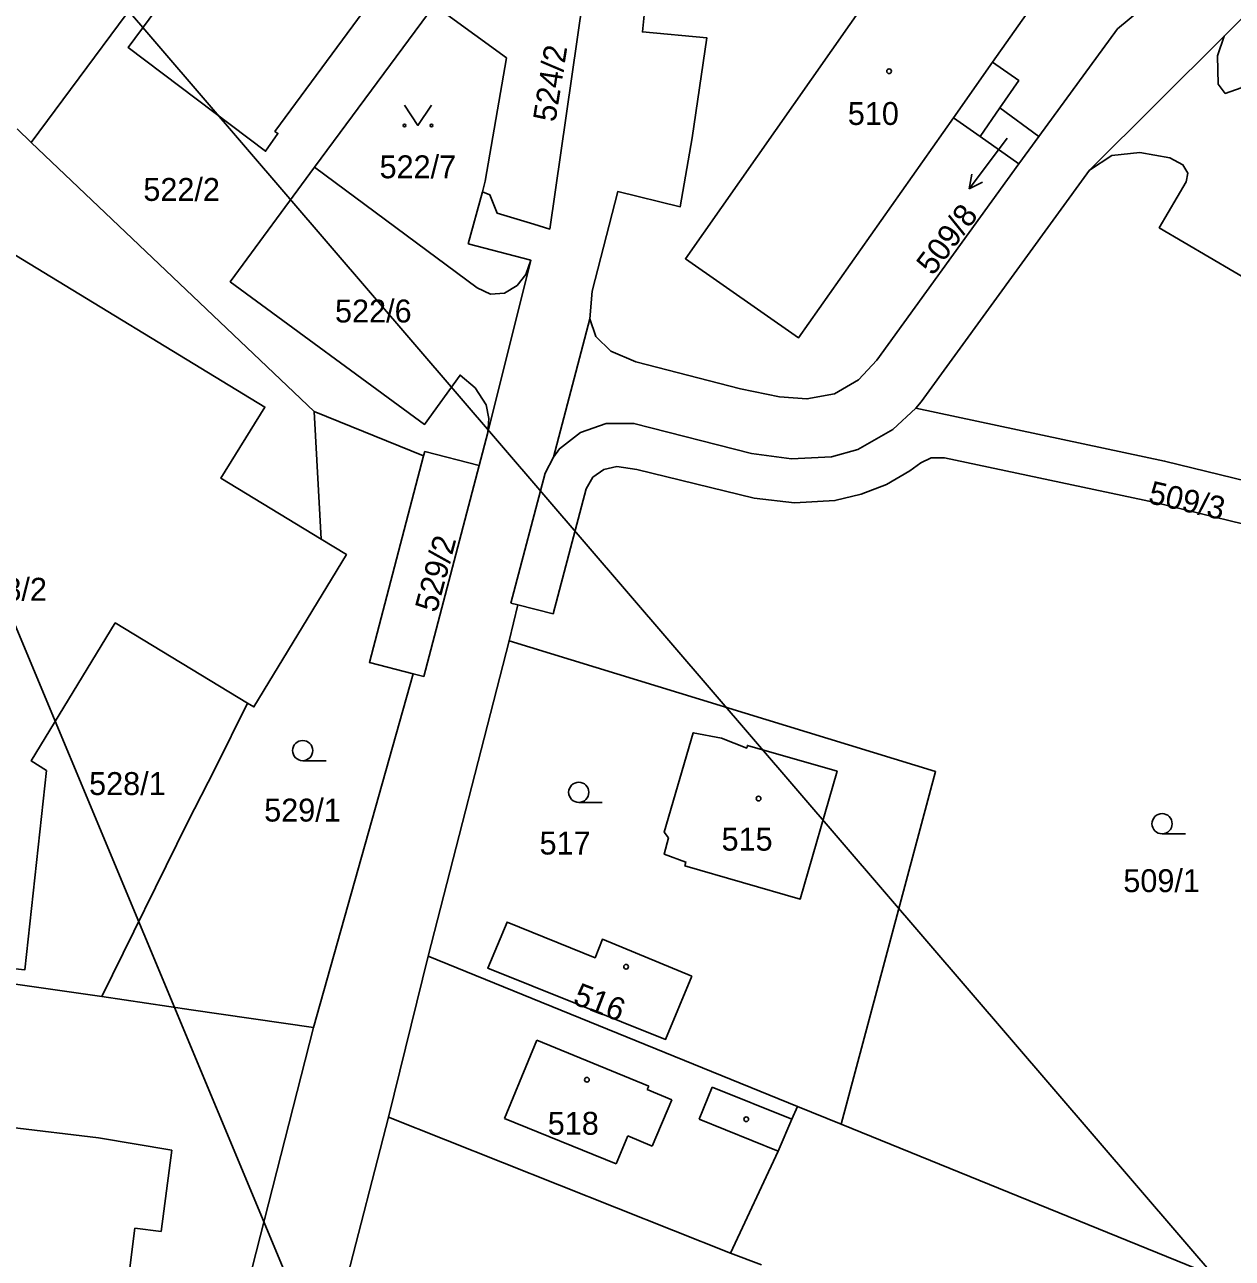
# Model space of a CAD drawing. Extents: x -558358 to -557517, y -1073786 to -1073189.
# Drawn here: x -558108 to -558018.3, y -1073559.5 to -1073467.9 of the extents above; entities that cross this region are included whole.
import ezdxf

# ---------------------------------------------------------------- set-up
doc = ezdxf.new("R2010")
doc.units = 0
for name, color, linetype in [('Hranice parcel', 7, 'Continuous'), ('Parcelní čísla', 7, 'Continuous'), ('Pop  PČ popisy', 7, 'Continuous'), ('Vnitřní kresba', 7, 'Continuous'), ('Vrstva 28', 7, 'Continuous'), ('Značky budov', 7, 'Continuous'), ('Značky kultur', 7, 'Continuous')]:
    doc.layers.add(name, color=color, linetype=linetype)

msp = doc.modelspace()

# ---------------------------------------------------------------- linework, layer by layer
at = {"layer": 'Hranice parcel'}
for p, q in [((-558086.45, -1073478.46), (-558077.57, -1073466.44)), ((-558076.9, -1073466.92), (-558072.2, -1073470.34)), ((-558018.89, -1073468.72), (-558028.88, -1073478.68)), ((-558072.2, -1073470.34), (-558073.77, -1073479.5)), ((-558037.01, -1073476.18), (-558035.54, -1073474.05)), ((-558032.65, -1073476.17), (-558035.54, -1073474.05)), ((-558108.55, -1073475.6), (-558107.49, -1073476.62)), ((-558107.49, -1073476.62), (-558086.48, -1073496.61)), ((-558037.01, -1073476.18), (-558034.12, -1073478.2)), ((-558032.65, -1073476.17), (-558034.12, -1073478.2)), ((-558073.77, -1073479.5), (-558073.98, -1073480.28)), ((-558073.98, -1073480.28), (-558075.03, -1073484.15)), ((-558075.03, -1073484.15), (-558070.38, -1073485.35)), ((-558070.38, -1073485.35), (-558073.57, -1073498.15)), ((-558068.7, -1073499.98), (-558066, -1073489.71)), ((-558085.97, -1073506.08), (-558086.48, -1073496.61)), ((-558086.48, -1073496.61), (-558078.35, -1073499.89)), ((-558074.22, -1073500.6), (-558073.57, -1073498.15)), ((-558078.35, -1073499.89), (-558078.27, -1073499.57)), ((-558078.27, -1073499.57), (-558074.22, -1073500.6)), ((-558074.22, -1073500.6), (-558078.34, -1073516.28)), ((-558071.35, -1073510.96), (-558071.87, -1073510.83)), ((-558071.35, -1073510.96), (-558072, -1073513.63)), ((-558068.72, -1073511.63), (-558071.35, -1073510.96)), ((-558072, -1073513.63), (-558078.01, -1073537.04)), ((-558079.12, -1073516.08), (-558086.54, -1073542.34)), ((-558078.34, -1073516.28), (-558079.12, -1073516.08)), ((-558102.24, -1073540.03), (-558132.14, -1073535.81)), ((-558078.01, -1073537.04), (-558080.96, -1073549.01)), ((-558078.01, -1073537.04), (-558050.57, -1073548.21)), ((-558050.57, -1073548.21), (-558047.33, -1073549.53)), ((-558080.96, -1073549.01), (-558086.83, -1073571.83)), ((-558080.96, -1073549.01), (-558055.56, -1073559.09)), ((-558055.56, -1073559.09), (-558053.26, -1073559.97))]:
    msp.add_line(p, q, dxfattribs=at)
for points in [[(-558066, -1073489.71), (-558065.83, -1073487.66), (-558063.93, -1073480.27), (-558059.28, -1073481.39), (-558058.41, -1073476.28), (-558057.32, -1073468.85), (-558062.09, -1073468.41), (-558061.69, -1073464.41), (-558056.9, -1073464.79), (-558056.8, -1073459.32), (-558057.06, -1073454.51), (-558057.72, -1073449.34), (-558062.47, -1073450), (-558063.26, -1073446.76)], [(-558069.01, -1073448.19), (-558089.39, -1073475.8), (-558089.17, -1073475.95), (-558090.09, -1073477.27), (-558100.29, -1073469.58), (-558095.61, -1073463.24)], [(-558018.89, -1073468.72), (-558017.43, -1073467.28), (-558004.36, -1073462.2), (-558000.71, -1073460.54), (-557997.38, -1073458.33), (-557994.81, -1073455.9), (-557993.5, -1073454.4)], [(-558035.54, -1073474.05), (-558034.14, -1073472.03), (-558036.08, -1073470.66), (-558030.24, -1073462.37), (-558038.66, -1073456.4), (-558058.9, -1073485.25), (-558050.49, -1073491.12), (-558038.98, -1073474.78), (-558037.01, -1073476.18)], [(-558066.82, -1073460.61), (-558066.53, -1073466.05), (-558068.98, -1073483.05), (-558070.17, -1073482.68), (-558072.89, -1073481.86), (-558073.42, -1073480.5), (-558073.98, -1073480.28)], [(-558095.61, -1073463.24), (-558096.89, -1073462.29), (-558107.49, -1073476.62)], [(-558022.54, -1073464.96), (-558025.08, -1073466.74), (-558026.8, -1073468.19), (-558032.65, -1073476.17)], [(-557958.67, -1073504.77), (-557959.52, -1073505.42), (-557960.94, -1073505.97), (-557962.48, -1073505.9), (-557963.93, -1073505.3), (-557964.34, -1073504.64), (-557964.29, -1073503.98), (-557962.25, -1073500.52), (-558015.64, -1073469.14), (-558017.62, -1073472.56), (-558018.8, -1073472.98), (-558019.32, -1073472.29), (-558019.38, -1073470.18), (-558018.89, -1073468.72)], [(-558028.88, -1073478.68), (-558027.22, -1073477.58), (-558025.14, -1073477.37), (-558022.91, -1073477.77), (-558021.94, -1073478.27), (-558021.58, -1073478.9), (-558021.69, -1073479.54), (-558023.7, -1073482.95), (-557975.42, -1073511.29), (-557973.41, -1073507.84), (-557972.71, -1073507.36), (-557971.95, -1073507.53), (-557966.49, -1073510.72), (-557965.39, -1073511.77), (-557964.96, -1073512.7), (-557964.79, -1073513.87)], [(-558073.57, -1073498.15), (-558073.51, -1073497.13), (-558073.7, -1073496.11), (-558074.52, -1073494.85), (-558075.64, -1073493.89), (-558078.28, -1073497.56), (-558092.71, -1073486.96), (-558086.45, -1073478.46)], [(-558070.38, -1073485.35), (-558070.76, -1073486.43), (-558071.41, -1073487.24), (-558072.33, -1073487.8), (-558073.38, -1073487.88), (-558074.36, -1073487.41), (-558086.45, -1073478.46)], [(-558034.12, -1073478.2), (-558044.67, -1073492.79), (-558046.03, -1073494.25), (-558047.82, -1073495.28), (-558049.88, -1073495.66), (-558051.92, -1073495.51), (-558054.81, -1073494.91), (-558062.59, -1073492.91), (-558064.44, -1073492.11), (-558065.56, -1073491.04), (-558066, -1073489.71)], [(-558028.88, -1073478.68), (-558041.38, -1073495.88), (-558041.79, -1073496.35)], [(-558091.42, -1073518.26), (-558101.25, -1073512.3), (-558107.5, -1073522.55), (-558106.36, -1073523.27), (-558107.97, -1073538.05), (-558111.12, -1073537.73), (-558112.87, -1073537.48), (-558114.81, -1073536.91), (-558116.94, -1073535.87), (-558118.99, -1073534.32), (-558120.94, -1073531.84), (-558122.18, -1073529.05), (-558122.71, -1073526.18), (-558122.56, -1073523.2), (-558121.01, -1073518.98), (-558124.91, -1073516.6), (-558126.01, -1073515.72), (-558126.67, -1073514.49), (-558126.79, -1073513.04), (-558126.28, -1073511.65), (-558109.74, -1073484.35), (-558090.14, -1073496.27), (-558093.41, -1073501.56), (-558085.97, -1073506.08)], [(-558068.7, -1073499.98), (-558068.26, -1073499.37), (-558066.7, -1073498.15), (-558064.79, -1073497.48), (-558062.72, -1073497.49), (-558053.98, -1073499.73), (-558051.03, -1073500.12), (-558048.06, -1073499.96), (-558046.1, -1073499.41), (-558043.49, -1073497.93), (-558041.79, -1073496.35)], [(-558041.79, -1073496.35), (-558023.3, -1073500.28), (-558002.91, -1073505.27), (-557995.6, -1073507.26), (-557965.43, -1073516.64)], [(-558078.35, -1073499.89), (-558082.38, -1073515.23), (-558079.12, -1073516.08)], [(-558071.87, -1073510.83), (-558069.32, -1073501.19), (-558068.7, -1073499.98)], [(-557987.27, -1073529.77), (-557989.29, -1073528.94), (-557986.56, -1073522.48), (-557986.36, -1073521.52), (-557986.44, -1073520.51), (-557989.6, -1073512.4), (-557996.64, -1073510.25), (-558004.14, -1073508.22), (-558024.01, -1073503.35), (-558039.66, -1073500.03), (-558040.64, -1073500.03), (-558041.42, -1073500.4), (-558042.23, -1073501), (-558043.97, -1073502.01), (-558045.84, -1073502.74), (-558047.8, -1073503.22), (-558050.8, -1073503.37), (-558053.79, -1073503.03), (-558062.52, -1073500.9), (-558063.99, -1073500.68), (-558064.96, -1073500.91), (-558065.77, -1073501.48), (-558066.28, -1073502.33), (-558068.72, -1073511.63)], [(-558091.42, -1073518.26), (-558090.96, -1073518.54), (-558084.08, -1073507.23), (-558085.97, -1073506.08)], [(-558047.33, -1073549.53), (-558040.31, -1073523.33), (-558072, -1073513.63)], [(-558102.24, -1073540.03), (-558095.9, -1073527.13), (-558093.83, -1073523.1), (-558091.42, -1073518.26)], [(-558060.16, -1073528.26), (-558060.48, -1073529.48), (-558058.86, -1073530.06), (-558058.94, -1073530.35), (-558050.37, -1073532.81), (-558047.63, -1073523.32), (-558054.29, -1073521.4), (-558054.34, -1073521.59), (-558056.23, -1073520.85), (-558058.32, -1073520.45), (-558060.47, -1073527.85), (-558060.16, -1073528.26)], [(-558058.43, -1073538.53), (-558065.06, -1073535.79), (-558065.61, -1073537.16), (-558072.15, -1073534.51), (-558073.59, -1073537.94), (-558060.37, -1073543.23), (-558058.43, -1073538.53)], [(-558086.54, -1073542.34), (-558095.62, -1073541.02), (-558102.24, -1073540.03)], [(-558099.6, -1073591.18), (-558091.09, -1073560.2), (-558086.54, -1073542.34)], [(-558055.56, -1073559.09), (-558052.02, -1073551.52), (-558051, -1073549.15), (-558050.57, -1073548.21)], [(-557977.41, -1073591.02), (-557981.5, -1073577.12), (-557984.25, -1073575.17), (-558047.33, -1073549.53)]]:
    msp.add_lwpolyline(points, dxfattribs=at)
at = {"layer": 'Pop  PČ popisy'}
for p, q in [((-558035, -1073476.29), (-558036.02, -1073477.67)), ((-558036.02, -1073477.67), (-558037.826, -1073480.067)), ((-558037.826, -1073480.067), (-558037.623, -1073478.966)), ((-558037.826, -1073480.067), (-558036.823, -1073479.568))]:
    msp.add_line(p, q, dxfattribs=at)
at = {"layer": 'Vnitřní kresba'}
for p, q in [((-558038.98, -1073474.78), (-558036.08, -1073470.66)), ((-558072.33, -1073549.11), (-558069.95, -1073543.28)), ((-558069.95, -1073543.28), (-558061.62, -1073546.69)), ((-558061.73, -1073546.96), (-558061.62, -1073546.69)), ((-558061.73, -1073546.96), (-558059.91, -1073547.71)), ((-558057.87, -1073549.14), (-558056.91, -1073546.78)), ((-558056.91, -1073546.78), (-558051, -1073549.15)), ((-558061.37, -1073551.16), (-558059.91, -1073547.71)), ((-558072.33, -1073549.11), (-558064.04, -1073552.48)), ((-558057.87, -1073549.14), (-558052.02, -1073551.52)), ((-558109.12, -1073549.75), (-558102.5, -1073550.54)), ((-558102.5, -1073550.54), (-558097.04, -1073551.46)), ((-558064.04, -1073552.48), (-558063.17, -1073550.4)), ((-558063.17, -1073550.4), (-558061.37, -1073551.16)), ((-558097.85, -1073557.5), (-558097.04, -1073551.46)), ((-558100.77, -1073564.79), (-558099.8, -1073557.24)), ((-558099.8, -1073557.24), (-558097.85, -1073557.5))]:
    msp.add_line(p, q, dxfattribs=at)
at = {"layer": 'Vrstva 28'}
for p, q in [((-558150.499, -1073408.333), (-557941.756, -1073651.484)), ((-558150.161, -1073413.052), (-558044.903, -1073665.427))]:
    msp.add_line(p, q, dxfattribs=at)
at = {"layer": 'Značky budov'}
for centre in [(-558043.767, -1073471.329), (-558053.467, -1073525.339), (-558063.307, -1073537.829), (-558066.217, -1073546.229), (-558054.377, -1073549.159)]:
    msp.add_circle(centre, 0.175, dxfattribs=at)
at = {"layer": 'Značky kultur'}
for p, q in [((-558087.333, -1073522.53), (-558085.583, -1073522.53)), ((-558066.823, -1073525.63), (-558065.073, -1073525.63)), ((-558023.493, -1073527.96), (-558021.743, -1073527.96))]:
    msp.add_line(p, q, dxfattribs=at)
msp.add_lwpolyline([(-558079.77, -1073473.859), (-558078.77, -1073475.36), (-558077.77, -1073473.859)], dxfattribs=at)
for centre, radius in [((-558079.77, -1073475.359), 0.1), ((-558077.77, -1073475.359), 0.1), ((-558087.333, -1073521.78), 0.75), ((-558066.823, -1073524.88), 0.75), ((-558023.493, -1073527.21), 0.75)]:
    msp.add_circle(centre, radius, dxfattribs=at)

# ---------------------------------------------------------------- texts
at = {"layer": 'Parcelní čísla'}
for s, rotation, p in [('524/2', 81, (-558068.556, -1073475.16)), ('509/8', 53, (-558040.516, -1073486.575)), ('509/3', 347, (-558024.595, -1073503.386)), ('529/2', 75, (-558077.378, -1073511.589)), ('516', 339, (-558067.335, -1073540.57))]:
    msp.add_text(s, height=1.7, rotation=rotation, dxfattribs=at).set_placement(p)
for s, p in [('510', (-558046.835, -1073475.32)), ('522/7', (-558081.62, -1073479.279)), ('522/2', (-558099.168, -1073480.96)), ('522/6', (-558084.93, -1073489.989)), ('528/2', (-558112.018, -1073510.65)), ('528/1', (-558103.198, -1073525.08)), ('529/1', (-558090.19, -1073527.05)), ('517', (-558069.735, -1073529.499)), ('515', (-558056.215, -1073529.21)), ('509/1', (-558026.368, -1073532.29)), ('518', (-558069.125, -1073550.31))]:
    msp.add_text(s, height=1.7, dxfattribs=at).set_placement(p)

doc.saveas('drawing.dxf')
